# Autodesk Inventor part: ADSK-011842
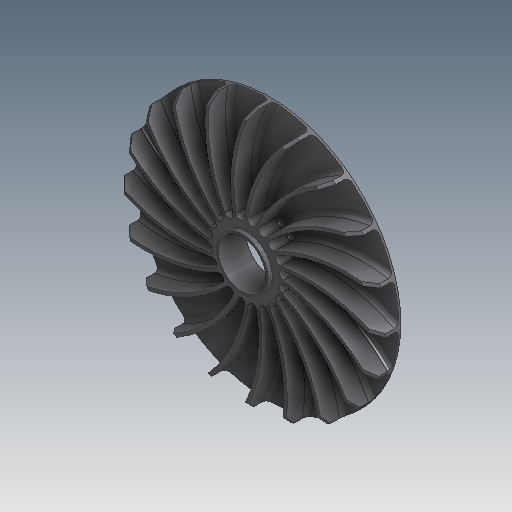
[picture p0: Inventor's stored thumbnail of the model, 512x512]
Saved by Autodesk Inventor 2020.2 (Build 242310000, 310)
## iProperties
Created: 2000-11
Part Number: ADSK-011842
Document SubType Name: Modeling
Designer: Martin Budgell
Material: Générique
Density: 1 g/cm^3
Appearance: Metal-Steel(Polish)
Mass: 30.4659 g
Surface Area: 415.447 cm^2
Volume: 30.4659 cm^3
Control State: 0
Master: False
Checked Out: False
Shininess: 60.0
Length Units: 11269
Angle Units: 11279
Time Units: 11290
Mass Units: 11283
Length Display Precision: 3
Angle Display Precision: 2
Compacted: True
Dimensions: 121,6x13x121,6 mm
Mass: 0,03 kg
VLT_Material: Generic
Density: 0.0
Volumn: 0.0
Area: 0.0
PropertySet Name: Model Information
Author: Martin Budgell
Revision Number: -
Title: ADSK-011842
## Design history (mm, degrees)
sketch "Sketch1"
  geometry: C1 r 60.808 at (-5.528, 0) reference; C2 r 11.112 at (-5.528, 0) reference
extrude "Extrusion1" new body sketch "Sketch1" distance "d0" = 13; taper "d1" = 0 deg
shell "Shell1" dims "d2" = 1
fillet "Fillet4" dims "d11" = 2
sketch "Sketch2"
  geometry: A1 r 12.112 centre (0, 0) between (-12.112, -0.024) and (-12.023, -1.473) reference; A2 r 60.808 centre (0, 0) between (-57.091, 20.934) and (-57.624, 19.419) reference; A3 r 69.283 centre (-7.281, 69.09) between (-57.091, 20.934) and (-12.112, -0.024); A4 r 70.722 centre (-7.281, 69.09) between (-57.624, 19.419) and (-12.023, -1.473)
  constraints: 8 point on circle, 2 centre point
extrude "Extrusion2" join sketch "Sketch2" distance "d3" = 10; taper "d4" = 0 deg
chamfer "Chamfer1" distance "d12" = 4; stored, may be unused: second distance "d13" = 4, angle "d14" = 45 deg
fillet "Fillet2" dims "d9" = 2
node "Solide1"
node "Corps solides"
node "Corps surfaciques"
pattern_circular "Circular Pattern1" dims angle "d8" = 360 deg
